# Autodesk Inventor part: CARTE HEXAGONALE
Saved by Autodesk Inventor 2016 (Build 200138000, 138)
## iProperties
Created: 2013-10
Part Number: CARTE HEXAGONALE
Material: Générique
Document SubType Name: Modeling
Designer: Bruno
Density: 1 g/cm^3
Appearance: Par défaut
Author: Bruno
Sending System: SolidWorks 2013
Last Author: christophe
Last Saved: 2014-02-15
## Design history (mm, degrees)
feature "Boss.-Extru.7" [Congé]
feature "Boss.-Extru.8" [Congé]
feature "Boss.-Extru.9" [Congé]
feature "Congé1"
node "Solide1"
node "Solide2"
node "Solide3"
node "Solide4"
